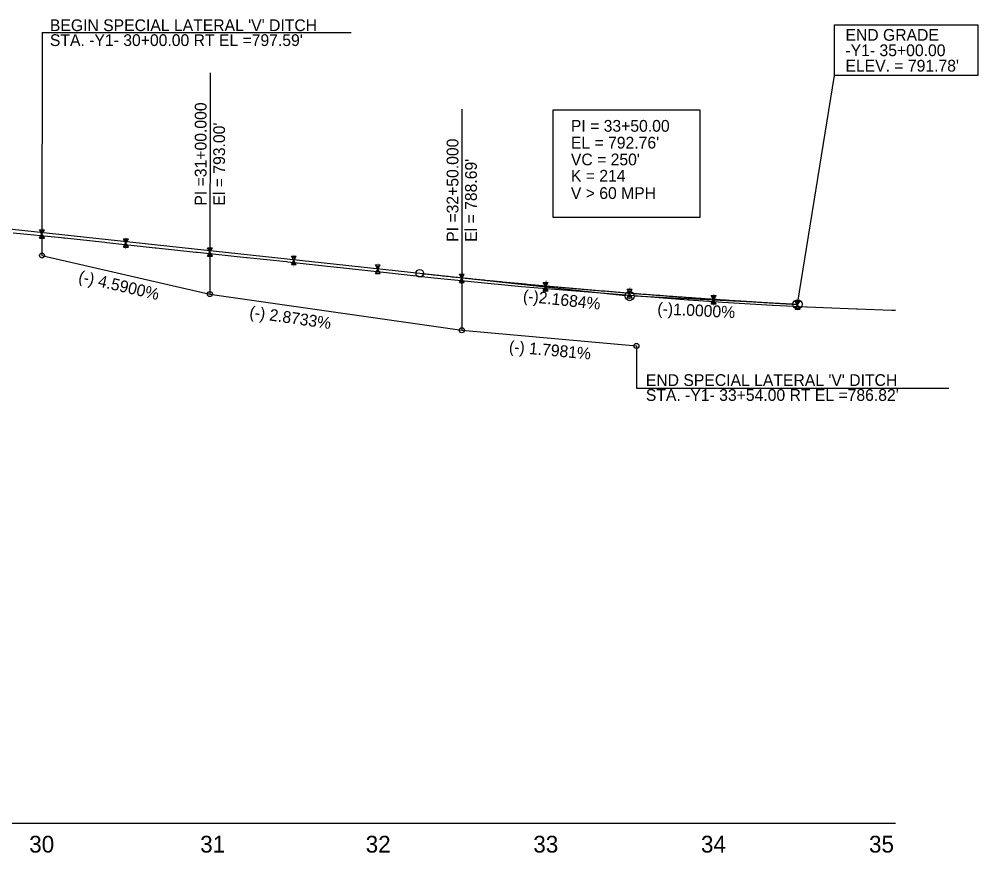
# Model space of a CAD drawing. Extents: x 579185 to 595036, y -53221 to -44640.
# Drawn here: x 581308 to 581879, y -48575 to -48078 of the extents above; entities that cross this region are included whole.
import ezdxf

# ---------------------------------------------------------------- set-up
doc = ezdxf.new("R2010")
doc.units = 0
for name, color, linetype in [('Exist Profile Cell', 7, 'Continuous'), ('Exist Vertical Profile Ground Line', 7, 'Continuous'), ('Exist Vertical Profile Horizontal Axis Label Major', 7, 'Continuous'), ('Old_Level_2', 7, 'Continuous'), ('Prop Grid Mask', 7, 'Continuous'), ('Prop Vertical Profile Curve Label', 7, 'Continuous'), ('Prop Vertical Profile Ditch Grade Right', 7, 'Continuous'), ('Prop Vertical Profile Ditch Grade Right Label', 7, 'Continuous'), ('Prop Vertical Profile Grade', 7, 'Continuous'), ('Prop Vertical Profile Grade Label', 7, 'Continuous'), ('Prop VPI Ditch Grade Right Label', 7, 'Continuous'), ('Prop VPI Label', 7, 'Continuous')]:
    doc.layers.add(name, color=color, linetype=linetype)

msp = doc.modelspace()

# ---------------------------------------------------------------- linework, layer by layer
at = {"layer": 'Exist Profile Cell'}
msp.add_line((579321.48, -48557.09), (581829.78, -48557.09), dxfattribs=at)
at = {"layer": 'Exist Vertical Profile Ground Line'}
for points in [[(581304.3, -48205.61), (581333.03, -48208.47), (581334.31, -48208.6), (581335.02, -48208.67), (581358.92, -48211.26), (581360.12, -48211.39), (581388.94, -48214.52), (581389.57, -48214.58), (581413.16, -48217.08), (581414.1, -48217.18), (581443.22, -48220.26), (581443.7, -48220.31)], [(581443.7, -48220.31), (581467.05, -48222.8), (581467.8, -48222.88), (581497.07, -48226.01), (581497.53, -48226.06), (581522.61, -48228.82), (581523.04, -48228.87), (581553.04, -48232.18), (581577.07, -48234.56), (581607.04, -48237.53), (581621.92, -48238.72), (581626.82, -48239.12), (581656.93, -48241.54), (581676.52, -48243.12), (581706.29, -48245.53), (581706.59, -48245.55), (581724.43, -48246.68), (581726.77, -48246.83), (581756.45, -48248.75), (581756.96, -48248.78), (581776.83, -48249.62), (581777.19, -48249.64), (581806.49, -48250.88), (581807.23, -48250.91), (581827.72, -48251.68), (581828.21, -48251.7), (581829.78, -48251.76)]]:
    msp.add_lwpolyline(points, dxfattribs=at)
at = {"layer": 'Old_Level_2'}
for p, q in [((581321.48, -48206.34), (581320.04, -48203.84)), ((581320.04, -48203.84), (581322.93, -48203.84)), ((581320.52, -48204.67), (581322.45, -48204.67)), ((581321.48, -48206.34), (581322.93, -48203.84)), ((581320.04, -48208.84), (581321.48, -48206.34)), ((581320.04, -48208.84), (581322.93, -48208.84)), ((581320.52, -48208.01), (581322.45, -48208.01)), ((581321, -48205.51), (581321.97, -48205.51)), ((581321, -48207.18), (581321.96, -48207.18)), ((581322.93, -48208.84), (581321.48, -48206.34)), ((581371.48, -48211.7), (581370.04, -48209.2)), ((581370.04, -48209.2), (581372.93, -48209.2)), ((581370.52, -48210.03), (581372.45, -48210.03)), ((581371, -48210.87), (581371.97, -48210.87)), ((581371.48, -48211.7), (581372.93, -48209.2)), ((581370.04, -48214.2), (581371.48, -48211.7)), ((581370.04, -48214.2), (581372.93, -48214.2)), ((581370.52, -48213.37), (581372.45, -48213.37)), ((581371, -48212.54), (581371.96, -48212.54)), ((581372.93, -48214.2), (581371.48, -48211.7)), ((581421.48, -48216.99), (581420.04, -48214.49)), ((581420.04, -48214.49), (581422.93, -48214.49)), ((581420.52, -48215.32), (581422.45, -48215.32)), ((581421, -48216.15), (581421.97, -48216.15)), ((581421.48, -48216.99), (581422.93, -48214.49)), ((581420.04, -48219.49), (581421.48, -48216.99)), ((581420.04, -48219.49), (581422.93, -48219.49)), ((581420.52, -48218.65), (581422.45, -48218.65)), ((581421, -48217.82), (581421.96, -48217.82)), ((581422.93, -48219.49), (581421.48, -48216.99)), ((581471.48, -48222.07), (581470.04, -48219.57)), ((581470.04, -48219.57), (581472.93, -48219.57)), ((581470.04, -48224.57), (581471.48, -48222.07)), ((581470.52, -48220.4), (581472.45, -48220.4)), ((581471, -48221.24), (581471.97, -48221.24)), ((581471.48, -48222.07), (581472.93, -48219.57)), ((581472.93, -48224.57), (581471.48, -48222.07)), ((581470.04, -48224.57), (581472.93, -48224.57)), ((581470.52, -48223.74), (581472.45, -48223.74)), ((581471, -48222.91), (581471.96, -48222.91)), ((581521.48, -48227.28), (581520.04, -48224.78)), ((581520.04, -48224.78), (581522.93, -48224.78)), ((581520.04, -48229.78), (581521.48, -48227.28)), ((581520.52, -48225.61), (581522.45, -48225.61)), ((581521, -48226.45), (581521.97, -48226.45)), ((581521, -48228.12), (581521.96, -48228.12)), ((581521.48, -48227.28), (581522.93, -48224.78)), ((581522.93, -48229.78), (581521.48, -48227.28)), ((581520.04, -48229.78), (581522.93, -48229.78)), ((581520.52, -48228.95), (581522.45, -48228.95)), ((581571.48, -48232.77), (581570.04, -48230.27)), ((581570.04, -48230.27), (581572.93, -48230.27)), ((581570.04, -48235.27), (581571.48, -48232.77)), ((581570.52, -48231.1), (581572.45, -48231.1)), ((581571, -48231.94), (581571.97, -48231.94)), ((581571, -48233.61), (581571.96, -48233.61)), ((581571.48, -48232.77), (581572.93, -48230.27)), ((581572.93, -48235.27), (581571.48, -48232.77)), ((581570.04, -48235.27), (581572.93, -48235.27)), ((581570.52, -48234.44), (581572.45, -48234.44)), ((581621.48, -48237.63), (581620.04, -48235.13)), ((581620.04, -48235.13), (581622.93, -48235.13)), ((581620.04, -48240.13), (581621.48, -48237.63)), ((581620.52, -48235.96), (581622.45, -48235.96)), ((581620.52, -48239.3), (581622.45, -48239.3)), ((581621, -48236.8), (581621.97, -48236.8)), ((581621, -48238.47), (581621.96, -48238.47)), ((581621.48, -48237.63), (581622.93, -48235.13)), ((581622.93, -48240.13), (581621.48, -48237.63)), ((581671.48, -48241.74), (581670.04, -48239.24)), ((581670.04, -48239.24), (581672.93, -48239.24)), ((581671.48, -48241.74), (581672.93, -48239.24)), ((581620.04, -48240.13), (581622.93, -48240.13)), ((581670.04, -48244.24), (581671.48, -48241.74)), ((581670.04, -48244.24), (581672.93, -48244.24)), ((581670.52, -48240.07), (581672.45, -48240.07)), ((581670.52, -48243.41), (581672.45, -48243.41)), ((581671, -48240.91), (581671.97, -48240.91)), ((581671, -48242.58), (581671.96, -48242.58)), ((581672.93, -48244.24), (581671.48, -48241.74)), ((581721.48, -48245.46), (581720.04, -48242.96)), ((581720.04, -48242.96), (581722.93, -48242.96)), ((581720.52, -48243.79), (581722.45, -48243.79)), ((581721, -48244.62), (581721.97, -48244.62)), ((581721.48, -48245.46), (581722.93, -48242.96)), ((581720.04, -48247.96), (581721.48, -48245.46)), ((581720.04, -48247.96), (581722.93, -48247.96)), ((581720.52, -48247.12), (581722.45, -48247.12)), ((581721, -48246.29), (581721.96, -48246.29)), ((581722.93, -48247.96), (581721.48, -48245.46)), ((581771.48, -48248.55), (581770.04, -48246.05)), ((581770.04, -48246.05), (581772.93, -48246.05)), ((581770.04, -48251.05), (581771.48, -48248.55)), ((581770.04, -48251.05), (581772.93, -48251.05)), ((581770.52, -48246.88), (581772.45, -48246.88)), ((581770.52, -48250.22), (581772.45, -48250.22)), ((581771, -48247.72), (581771.97, -48247.72)), ((581771, -48249.39), (581771.96, -48249.39)), ((581771.48, -48248.55), (581772.93, -48246.05)), ((581772.93, -48251.05), (581771.48, -48248.55))]:
    msp.add_line(p, q, dxfattribs=at)
at = {"layer": 'Prop Grid Mask'}
for points in [[(581793.44, -48081.78), (581878.84, -48081.78), (581878.84, -48111.97), (581793.44, -48111.97)], [(581625.83, -48132.33), (581713.19, -48132.33), (581713.19, -48196.51), (581625.83, -48196.51)]]:
    msp.add_lwpolyline(points, close=True, dxfattribs=at)
at = {"layer": 'Prop Vertical Profile Curve Label'}
msp.add_line((581771.48, -48248.2), (581793.44, -48111.97), dxfattribs=at)
msp.add_circle((581546.48, -48229.72), 2.25, dxfattribs=at)
at = {"layer": 'Prop Vertical Profile Ditch Grade Right'}
msp.add_lwpolyline([(581321.48, -48219.14), (581421.48, -48242.09), (581571.48, -48263.64), (581675.48, -48272.99)], dxfattribs=at)
at = {"layer": 'Prop Vertical Profile Ditch Grade Right Label'}
for p, q in [((581321.6, -48086.38), (581321.48, -48219.14)), ((581321.6, -48086.38), (581505.59, -48086.38)), ((581421.6, -48110.4), (581421.48, -48242.09)), ((581571.6, -48131.95), (581571.48, -48263.64)), ((581675.48, -48272.99), (581675.46, -48298.17)), ((581675.46, -48298.17), (581861.66, -48298.17))]:
    msp.add_line(p, q, dxfattribs=at)
at = {"layer": 'Prop Vertical Profile Grade'}
msp.add_line((581296.48, -48202.62), (581546.48, -48229.72), dxfattribs=at)
msp.add_spline([(581546.48, -48229.72), (581550.98, -48230.21), (581555.48, -48230.69), (581559.98, -48231.17), (581564.48, -48231.64), (581568.98, -48232.1), (581573.48, -48232.57), (581577.98, -48233.02), (581582.48, -48233.47), (581586.98, -48233.92), (581591.48, -48234.37), (581595.98, -48234.8), (581600.48, -48235.24), (581604.98, -48235.67), (581609.48, -48236.09), (581613.98, -48236.51), (581618.48, -48236.92), (581622.98, -48237.33), (581627.48, -48237.74), (581631.98, -48238.14), (581636.48, -48238.53), (581640.98, -48238.93), (581645.48, -48239.31), (581649.98, -48239.69), (581654.48, -48240.07), (581658.98, -48240.44), (581663.48, -48240.81), (581667.98, -48241.17), (581672.48, -48241.53), (581676.98, -48241.88), (581681.48, -48242.23), (581685.98, -48242.57), (581690.48, -48242.91), (581694.98, -48243.25), (581699.48, -48243.58), (581703.98, -48243.9), (581708.48, -48244.22), (581712.98, -48244.54), (581717.48, -48244.85), (581721.98, -48245.15), (581726.48, -48245.45), (581730.98, -48245.75), (581735.48, -48246.04), (581739.98, -48246.33), (581744.48, -48246.61), (581748.98, -48246.89), (581753.48, -48247.16), (581757.98, -48247.43), (581762.48, -48247.69), (581766.98, -48247.95), (581771.48, -48248.2)], degree=3, dxfattribs=at)
at = {"layer": 'Prop VPI Ditch Grade Right Label'}
for centre in [(581321.48, -48219.14), (581421.48, -48242.09), (581571.48, -48263.64), (581675.48, -48272.99)]:
    msp.add_circle(centre, 1.5, dxfattribs=at)
at = {"layer": 'Prop VPI Label'}
for p, q in [((581546.48, -48229.72), (581668.75, -48242.98)), ((581768.74, -48248.14), (581674.23, -48243.41))]:
    msp.add_line(p, q, dxfattribs=at)
for centre in [(581671.48, -48243.28), (581771.48, -48248.2)]:
    msp.add_circle(centre, 2.75, dxfattribs=at)

# ---------------------------------------------------------------- texts
at = {"layer": 'Exist Vertical Profile Horizontal Axis Label Major'}
for s, p in [('30', (581313.87, -48574.59)), ('31', (581415.71, -48574.59)), ('32', (581514.26, -48574.59)), ('33', (581614.09, -48574.59)), ('34', (581713.93, -48574.59)), ('35', (581814.03, -48574.59))]:
    msp.add_text(s, height=10, dxfattribs=at).set_placement(p)
at = {"layer": 'Old_Level_2'}
for p in [(581321.25, -48203.68), (581321.06, -48209.85), (581371.25, -48209.04), (581371.06, -48215.21), (581421.25, -48214.33), (581421.06, -48220.49), (581471.25, -48219.41), (581471.06, -48225.58), (581521.25, -48224.62), (581521.06, -48230.79), (581571.25, -48230.11), (581571.06, -48236.28), (581621.25, -48234.97), (581671.25, -48239.08), (581621.06, -48241.14), (581671.06, -48245.25), (581721.25, -48242.8), (581771.25, -48245.89), (581721.06, -48248.96), (581771.06, -48252.06)]:
    msp.add_text('6"', height=0.8, dxfattribs=at).set_placement(p)
at = {"layer": 'Prop Vertical Profile Curve Label'}
for s, p in [("VC = 250'", (581636.48, -48165.45)), ('K = 214', (581636.48, -48175.14)), ('V > 60 MPH', (581636.48, -48185.47))]:
    msp.add_text(s, height=7, dxfattribs=at).set_placement(p)
at = {"layer": 'Prop Vertical Profile Ditch Grade Right'}
for s, p in [("BEGIN SPECIAL LATERAL 'V' DITCH", (581326.19, -48085.55)), ("STA. -Y1- 30+00.00 RT EL =797.59'", (581326.19, -48094.42)), ("END SPECIAL LATERAL 'V' DITCH", (581681.11, -48296.81)), ("STA. -Y1- 33+54.00 RT EL =786.82'", (581681.11, -48305.68))]:
    msp.add_text(s, height=7, dxfattribs=at).set_placement(p)
at = {"layer": 'Prop Vertical Profile Ditch Grade Right Label'}
for s, rotation, p in [('(-) 4.5900%', 347.0744, (581342.72, -48234.79)), ('(-) 2.8733%', 351.8244, (581444.73, -48256.04)), ('(-) 1.7981%', 354.8627, (581599.39, -48276.69))]:
    msp.add_text(s, height=7, rotation=rotation, dxfattribs=at).set_placement(p)
at = {"layer": 'Prop Vertical Profile Grade Label'}
for s, rotation, p in [('(-)2.1684%', 353.8121, (581607.68, -48246.42)), ('(-)1.0000%', 357.1376, (581687.87, -48254.11))]:
    msp.add_text(s, height=7, rotation=rotation, dxfattribs=at).set_placement(p)
at = {"layer": 'Prop VPI Ditch Grade Right Label'}
for s, p in [('PI =31+00.000', (581419.48, -48189.42)), ("El = 793.00'", (581430.48, -48189.42)), ('PI =32+50.000', (581569.48, -48210.97)), ("El = 788.69'", (581580.48, -48210.97))]:
    msp.add_text(s, height=7, rotation=90, dxfattribs=at).set_placement(p)
at = {"layer": 'Prop VPI Label'}
for s, p in [('END GRADE', (581799.99, -48091.29)), ('-Y1- 35+00.00', (581799.99, -48100.46)), ("ELEV. = 791.78'", (581799.99, -48109.64)), ('PI = 33+50.00', (581636.48, -48145.45)), ("EL = 792.76'", (581636.48, -48155.45))]:
    msp.add_text(s, height=7, dxfattribs=at).set_placement(p)

doc.saveas('drawing.dxf')
